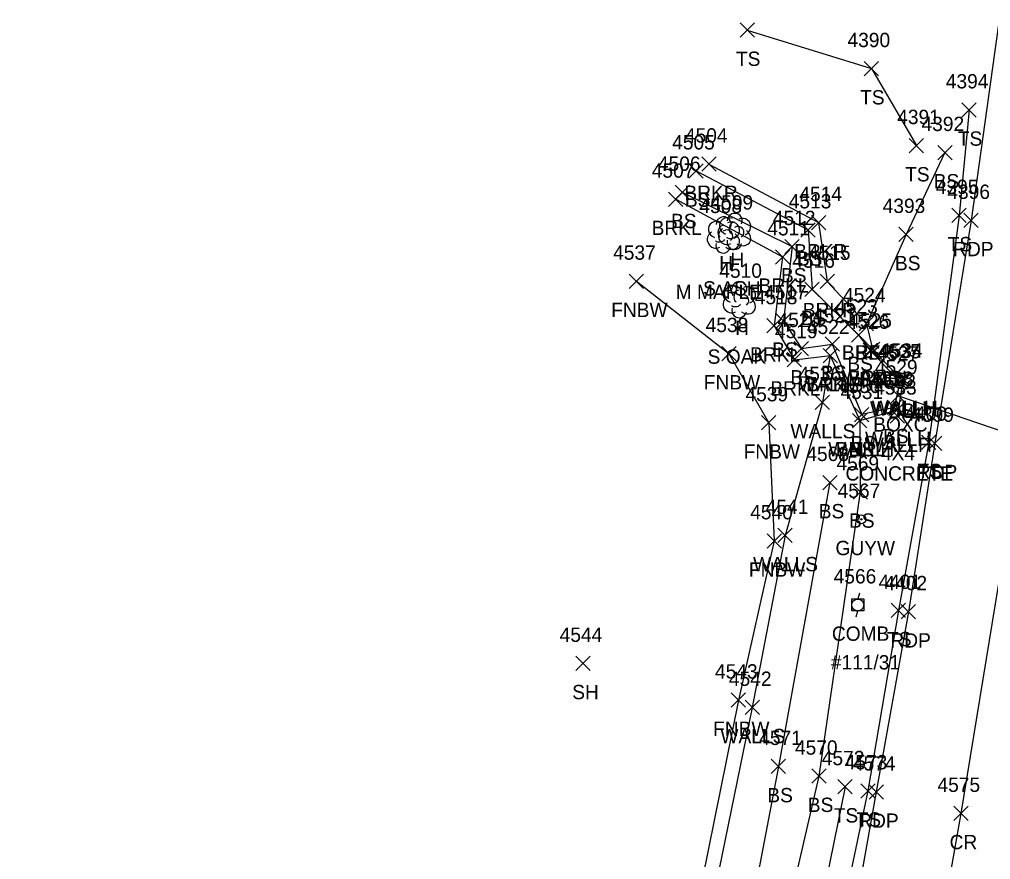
# Model space of a CAD drawing. Extents: x 1678863 to 1683592, y 407783 to 418211.
# Drawn here: x 1680132.2 to 1680267.7, y 412706.9 to 412824.2 of the extents above; entities that cross this region are included whole.
import ezdxf

# ---------------------------------------------------------------- set-up
doc = ezdxf.new("R2010")
doc.units = 0
for name, color, linetype in [('D_A', 7, 'Continuous'), ('D_C', 7, 'Continuous'), ('D_I', 7, 'Continuous'), ('D_TIC', 7, 'Continuous'), ('DDEFAULT', 7, 'Continuous'), ('DHW', 7, 'Continuous'), ('L_A', 7, 'Continuous'), ('L_C', 7, 'Continuous'), ('L_I', 7, 'Continuous'), ('L_TIC', 7, 'Continuous'), ('LAWE', 7, 'Continuous'), ('LELB', 7, 'Continuous'), ('LFNC', 7, 'Continuous'), ('LTD', 7, 'Continuous'), ('LWS', 7, 'Continuous'), ('P_A', 7, 'Continuous'), ('P_I', 7, 'Continuous'), ('P_TIC', 7, 'Continuous'), ('PET', 7, 'Continuous'), ('PRC', 7, 'Continuous'), ('U_A', 7, 'Continuous'), ('U_C', 7, 'Continuous'), ('U_I', 7, 'Continuous'), ('UP', 7, 'Continuous'), ('UPGW', 7, 'Continuous')]:
    doc.layers.add(name, color=color, linetype=linetype)

msp = doc.modelspace()

# ---------------------------------------------------------------- linework, layer by layer
at = {"layer": 'D_TIC'}
for points in [[(1680250.28, 412777.16), (1680252.28, 412779.16)], [(1680252.28, 412777.16), (1680250.28, 412779.16)], [(1680254.33, 412772.88), (1680256.33, 412774.88)], [(1680256.33, 412772.88), (1680254.33, 412774.88)], [(1680254.58, 412772.97), (1680256.58, 412774.97)], [(1680256.58, 412772.97), (1680254.58, 412774.97)], [(1680253.88, 412770.66), (1680255.88, 412772.66)], [(1680255.88, 412770.66), (1680253.88, 412772.66)], [(1680253.63, 412768.64), (1680255.63, 412770.64)], [(1680255.63, 412768.64), (1680253.63, 412770.64)], [(1680253.75, 412767.82), (1680255.75, 412769.82)], [(1680255.75, 412767.82), (1680253.75, 412769.82)], [(1680248.49, 412767.2), (1680250.49, 412769.2)], [(1680250.49, 412767.2), (1680248.49, 412769.2)]]:
    msp.add_lwpolyline(points, dxfattribs=at)
at = {"layer": 'DDEFAULT'}
msp.add_lwpolyline([(1680254.88, 412771.66), (1680298.09, 412756.89)], dxfattribs=at)
at = {"layer": 'DHW'}
for points in [[(1680251.28, 412778.16), (1680255.33, 412773.88)], [(1680254.75, 412768.82), (1680255.58, 412773.97)], [(1680249.49, 412768.2), (1680254.63, 412769.64)]]:
    msp.add_lwpolyline(points, dxfattribs=at)
at = {"layer": 'L_TIC'}
for points in [[(1680232.8, 412821.69), (1680234.8, 412823.69)], [(1680234.8, 412821.69), (1680232.8, 412823.69)], [(1680250.13, 412816.31), (1680252.13, 412818.31)], [(1680252.13, 412816.31), (1680250.13, 412818.31)], [(1680263.76, 412810.55), (1680265.76, 412812.55)], [(1680265.76, 412810.55), (1680263.76, 412812.55)], [(1680256.41, 412805.57), (1680258.41, 412807.57)], [(1680258.41, 412805.57), (1680256.41, 412807.57)], [(1680260.37, 412804.6), (1680262.37, 412806.6)], [(1680262.37, 412804.6), (1680260.37, 412806.6)], [(1680227.43, 412802.99), (1680229.43, 412804.99)], [(1680229.43, 412802.99), (1680227.43, 412804.99)], [(1680225.65, 412802.03), (1680227.65, 412804.03)], [(1680227.65, 412802.03), (1680225.65, 412804.03)], [(1680223.71, 412799.05), (1680225.71, 412801.05)], [(1680225.71, 412799.05), (1680223.71, 412801.05)], [(1680222.8, 412798.09), (1680224.8, 412800.09)], [(1680224.8, 412798.09), (1680222.8, 412800.09)], [(1680262.36, 412795.82), (1680264.36, 412797.82)], [(1680264.36, 412795.82), (1680262.36, 412797.82)], [(1680242.75, 412794.82), (1680244.75, 412796.82)], [(1680244.75, 412794.82), (1680242.75, 412796.82)], [(1680241.27, 412793.8), (1680243.27, 412795.8)], [(1680243.27, 412793.8), (1680241.27, 412795.8)], [(1680254.95, 412793.17), (1680256.95, 412795.17)], [(1680256.95, 412793.17), (1680254.95, 412795.17)], [(1680239.05, 412791.47), (1680241.05, 412793.47)], [(1680241.05, 412791.47), (1680239.05, 412793.47)], [(1680237.71, 412790.04), (1680239.71, 412792.04)], [(1680239.71, 412790.04), (1680237.71, 412792.04)], [(1680217.33, 412786.64), (1680219.33, 412788.64)], [(1680219.33, 412786.64), (1680217.33, 412788.64)], [(1680243.95, 412786.62), (1680245.95, 412788.62)], [(1680245.95, 412786.62), (1680243.95, 412788.62)], [(1680241.83, 412785.52), (1680243.83, 412787.52)], [(1680243.83, 412785.52), (1680241.83, 412787.52)], [(1680237.83, 412781.11), (1680239.83, 412783.11)], [(1680239.83, 412781.11), (1680237.83, 412783.11)], [(1680236.53, 412780.43), (1680238.53, 412782.43)], [(1680238.53, 412780.43), (1680236.53, 412782.43)], [(1680249.41, 412780.71), (1680251.41, 412782.71)], [(1680251.41, 412780.71), (1680249.41, 412782.71)], [(1680249.41, 412780.71), (1680251.41, 412782.71)], [(1680251.41, 412780.71), (1680249.41, 412782.71)], [(1680248.32, 412779.13), (1680250.32, 412781.13)], [(1680250.32, 412779.13), (1680248.32, 412781.13)], [(1680240.36, 412777.24), (1680242.36, 412779.24)], [(1680242.36, 412777.24), (1680240.36, 412779.24)], [(1680244.66, 412777.88), (1680246.66, 412779.88)], [(1680246.66, 412777.88), (1680244.66, 412779.88)], [(1680249.98, 412776.99), (1680251.98, 412778.99)], [(1680251.98, 412776.99), (1680249.98, 412778.99)], [(1680250.28, 412777.16), (1680252.28, 412779.16)], [(1680252.28, 412777.16), (1680250.28, 412779.16)], [(1680230.24, 412776.54), (1680232.24, 412778.54)], [(1680232.24, 412776.54), (1680230.24, 412778.54)], [(1680239.37, 412775.69), (1680241.37, 412777.69)], [(1680241.37, 412775.69), (1680239.37, 412777.69)], [(1680244.37, 412776.27), (1680246.37, 412778.27)], [(1680246.37, 412776.27), (1680244.37, 412778.27)], [(1680244.37, 412776.27), (1680246.37, 412778.27)], [(1680246.37, 412776.27), (1680244.37, 412778.27)], [(1680254.09, 412772.57), (1680256.09, 412774.57)], [(1680256.09, 412772.57), (1680254.09, 412774.57)], [(1680243.27, 412769.72), (1680245.27, 412771.72)], [(1680245.27, 412769.72), (1680243.27, 412771.72)], [(1680253.31, 412769.03), (1680255.31, 412771.03)], [(1680255.31, 412769.03), (1680253.31, 412771.03)], [(1680248.77, 412768.04), (1680250.77, 412770.04)], [(1680250.77, 412768.04), (1680248.77, 412770.04)], [(1680248.77, 412768.04), (1680250.77, 412770.04)], [(1680250.77, 412768.04), (1680248.77, 412770.04)], [(1680235.8, 412766.88), (1680237.8, 412768.88)], [(1680237.8, 412766.88), (1680235.8, 412768.88)], [(1680248.49, 412767.2), (1680250.49, 412769.2)], [(1680250.49, 412767.2), (1680248.49, 412769.2)], [(1680248.49, 412767.2), (1680250.49, 412769.2)], [(1680250.49, 412767.2), (1680248.49, 412769.2)], [(1680258.13, 412764.17), (1680260.13, 412766.17)], [(1680260.13, 412764.17), (1680258.13, 412766.17)], [(1680244.33, 412758.55), (1680246.33, 412760.55)], [(1680246.33, 412758.55), (1680244.33, 412760.55)], [(1680248.55, 412757.24), (1680250.55, 412759.24)], [(1680250.55, 412757.24), (1680248.55, 412759.24)], [(1680238.06, 412751.16), (1680240.06, 412753.16)], [(1680240.06, 412751.16), (1680238.06, 412753.16)], [(1680236.55, 412750.41), (1680238.55, 412752.41)], [(1680238.55, 412750.41), (1680236.55, 412752.41)], [(1680253.89, 412740.7), (1680255.89, 412742.7)], [(1680255.89, 412740.7), (1680253.89, 412742.7)], [(1680209.87, 412733.31), (1680211.87, 412735.31)], [(1680211.87, 412733.31), (1680209.87, 412735.31)], [(1680231.55, 412728.19), (1680233.55, 412730.19)], [(1680233.55, 412728.19), (1680231.55, 412730.19)], [(1680233.49, 412727.17), (1680235.49, 412729.17)], [(1680235.49, 412727.17), (1680233.49, 412729.17)], [(1680237.15, 412718.92), (1680239.15, 412720.92)], [(1680239.15, 412718.92), (1680237.15, 412720.92)], [(1680242.8, 412717.57), (1680244.8, 412719.57)], [(1680244.8, 412717.57), (1680242.8, 412719.57)], [(1680246.45, 412716.1), (1680248.45, 412718.1)], [(1680248.45, 412716.1), (1680246.45, 412718.1)], [(1680249.64, 412715.52), (1680251.64, 412717.52)], [(1680251.64, 412715.52), (1680249.64, 412717.52)]]:
    msp.add_lwpolyline(points, dxfattribs=at)
at = {"layer": 'LAWE'}
for points in [[(1680228.43, 412803.99), (1680243.75, 412795.82), (1680244.95, 412787.62), (1680250.41, 412781.71), (1680251.28, 412778.16)], [(1680223.8, 412799.09), (1680238.71, 412791.04), (1680237.53, 412781.43), (1680240.37, 412776.69), (1680245.37, 412777.27), (1680249.49, 412768.2)]]:
    msp.add_lwpolyline(points, dxfattribs=at)
at = {"layer": 'LELB'}
for points in [[(1680233.8, 412822.69), (1680251.13, 412817.31), (1680257.41, 412806.57)], [(1680264.76, 412811.55), (1680263.36, 412796.82), (1680259.13, 412765.17), (1680254.89, 412741.7), (1680250.64, 412716.52), (1680241.43, 412672.74), (1680233.74, 412632.17), (1680225.8, 412592.02), (1680220.98, 412567.08), (1680215.74, 412540.31), (1680209.94, 412509.25), (1680204.22, 412481.07), (1680197.27, 412449.21), (1680193.18, 412427.19), (1680186.13, 412390.36), (1680174.63, 412348.27), (1680162.56, 412311.44), (1680153.21, 412285.21), (1680144.52, 412262.81), (1680134.21, 412242.14)], [(1680261.37, 412805.6), (1680255.95, 412794.17), (1680250.41, 412781.71)], [(1680226.65, 412803.03), (1680242.27, 412794.8), (1680242.83, 412786.52), (1680249.32, 412780.13), (1680250.98, 412777.99), (1680255.09, 412773.57), (1680254.31, 412770.03), (1680249.77, 412769.04)], [(1680224.71, 412800.05), (1680240.05, 412792.47), (1680238.83, 412782.11), (1680241.36, 412778.24), (1680245.66, 412778.88), (1680249.77, 412769.04)], [(1680249.49, 412768.2), (1680249.55, 412758.24), (1680243.8, 412718.57), (1680233.25, 412673.09), (1680225.51, 412631.52), (1680218.17, 412594.23), (1680214.71, 412567.57), (1680210.01, 412541.36), (1680205.47, 412510.43), (1680201.22, 412481.17), (1680196.31, 412449.36), (1680192.42, 412427.44), (1680185.73, 412390.56), (1680174.21, 412348.31), (1680162.14, 412311.42), (1680152.66, 412285.29), (1680142.36, 412263.76), (1680132.21, 412242.7)], [(1680245.33, 412759.55), (1680238.15, 412719.92), (1680229.05, 412672.21), (1680221.09, 412632.34), (1680212.81, 412594.54), (1680208.5, 412568.01), (1680206.55, 412542.12), (1680201.64, 412511.16), (1680199.02, 412481.87), (1680194.17, 412449.89), (1680191.64, 412427.54), (1680187.79, 412410.87)], [(1680247.45, 412717.1), (1680238.47, 412672.98), (1680230.77, 412632.28), (1680223.41, 412592.33), (1680217.93, 412566.73), (1680212.88, 412540.48)]]:
    msp.add_lwpolyline(points, dxfattribs=at)
at = {"layer": 'LFNC'}
msp.add_lwpolyline([(1680218.33, 412787.64), (1680231.24, 412777.54), (1680236.8, 412767.88), (1680237.55, 412751.41), (1680232.55, 412729.19), (1680224.98, 412691.69), (1680216.02, 412647.3), (1680207.26, 412604.15), (1680201.33, 412570.32), (1680196.34, 412553.95), (1680191.84, 412524.59), (1680188.15, 412511.78), (1680185.17, 412500.91), (1680174.35, 412504.66)], dxfattribs=at)
at = {"layer": 'LTD'}
for p, q in [((1680230.45, 412794.15), (1680230.45, 412794.15)), ((1680230.45, 412794.15), (1680230.45, 412794.15)), ((1680232, 412794.64), (1680232, 412794.64)), ((1680232, 412794.64), (1680232, 412794.64)), ((1680232.67, 412785.12), (1680232.67, 412785.12)), ((1680232.67, 412785.12), (1680232.67, 412785.12))]:
    msp.add_line(p, q, dxfattribs=at)
for centre in [(1680230.49, 412795.58), (1680232.05, 412796.07), (1680232.71, 412786.55)]:
    msp.add_arc(centre, 1.05, 335.5272, 180.9563, dxfattribs=at)
for centre, major_axis, ratio, start_param, end_param in [((1680231.21, 412795.3), (1.21, -0.51), 0.895232, 1.570796, 4.712389), ((1680233.05, 412795.22), (-1.14, -0.48), 0.949671, 1.570796, 4.712389), ((1680229.66, 412794.82), (1.21, -0.51), 0.895232, 1.570796, 4.712389), ((1680230.24, 412794.61), (-0.208, -0.792), 0.645439, 3.141593, 6.283185), ((1680231.49, 412794.73), (-1.14, -0.48), 0.949671, 1.570796, 4.712389), ((1680231.8, 412795.09), (-0.208, -0.792), 0.645439, 3.141593, 6.283185), ((1680232.5, 412794.47), (-0.5, 0.667), 0.989748, 3.141593, 6.283185), ((1680229.36, 412793.44), (0.58, -1.04), 0.959034, 3.141593, 6.283185), ((1680230.92, 412793.93), (0.58, -1.04), 0.959034, 3.141593, 6.283185), ((1680230.95, 412793.98), (-0.5, 0.667), 0.989748, 3.141593, 6.283185), ((1680231.45, 412793.32), (-1.09, 0.79), 0.841452, 1.570796, 4.712389), ((1680231.55, 412793.88), (-0.625, -0.083), 0.423636, 0, 3.141593), ((1680233, 412793.8), (-1.09, 0.79), 0.841452, 1.570796, 4.712389), ((1680230.45, 412792.65), (0.26, 1.06), 0.942809, 1.570796, 4.712389), ((1680229.99, 412793.4), (-0.625, -0.083), 0.423636, 0, 3.141593), ((1680232, 412793.14), (0.26, 1.06), 0.942809, 1.570796, 4.712389), ((1680231.87, 412785.78), (1.21, -0.51), 0.895232, 1.570796, 4.712389), ((1680233.71, 412785.7), (-1.14, -0.48), 0.949671, 1.570796, 4.712389), ((1680232.46, 412785.58), (-0.208, -0.792), 0.645439, 3.141593, 6.283185), ((1680233.17, 412784.95), (-0.5, 0.667), 0.989748, 3.141593, 6.283185), ((1680231.58, 412784.41), (0.58, -1.04), 0.959034, 3.141593, 6.283185), ((1680232.21, 412784.37), (-0.625, -0.083), 0.423636, 0, 3.141593), ((1680233.67, 412784.28), (-1.09, 0.79), 0.841452, 1.570796, 4.712389), ((1680232.67, 412783.62), (0.26, 1.06), 0.942809, 1.570796, 4.712389)]:
    msp.add_ellipse(centre, major_axis=major_axis, ratio=ratio, start_param=start_param, end_param=end_param, dxfattribs=at)
at = {"layer": 'LWS'}
msp.add_lwpolyline([(1680245.37, 412777.27), (1680244.27, 412770.72), (1680239.06, 412752.16), (1680234.49, 412728.17), (1680226.88, 412691.09), (1680218.1, 412646.92), (1680208.94, 412603.49), (1680203.86, 412570.61), (1680197.52, 412543.94), (1680191.67, 412514.8), (1680187.87, 412497.52)], dxfattribs=at)
at = {"layer": 'P_TIC'}
for points in [[(1680264.04, 412795.13), (1680266.04, 412797.13)], [(1680266.04, 412795.13), (1680264.04, 412797.13)], [(1680258.96, 412764.02), (1680260.96, 412766.02)], [(1680260.96, 412764.02), (1680258.96, 412766.02)], [(1680255.28, 412740.52), (1680257.28, 412742.52)], [(1680257.28, 412740.52), (1680255.28, 412742.52)], [(1680250.79, 412715.36), (1680252.79, 412717.36)], [(1680252.79, 412715.36), (1680250.79, 412717.36)], [(1680262.6, 412712.37), (1680264.6, 412714.37)], [(1680264.6, 412712.37), (1680262.6, 412714.37)]]:
    msp.add_lwpolyline(points, dxfattribs=at)
at = {"layer": 'PET'}
msp.add_lwpolyline([(1680269.63, 412829.2), (1680265.04, 412796.13), (1680259.96, 412765.02), (1680256.28, 412741.52), (1680251.79, 412716.36), (1680243.91, 412672.27), (1680235.73, 412631.6), (1680228.05, 412591.55), (1680223.07, 412565.97), (1680218.11, 412539.91), (1680211.61, 412508.58), (1680205.85, 412480.93), (1680199.66, 412448.83), (1680195.01, 412427.07), (1680186.54, 412390.39), (1680175.26, 412348.31), (1680163.41, 412311.1), (1680153.81, 412285.2), (1680145.32, 412262.57), (1680136.24, 412241.39)], dxfattribs=at)
at = {"layer": 'PRC'}
msp.add_lwpolyline([(1680281.38, 412827.12), (1680276.54, 412794.32), (1680271.51, 412761.65), (1680263.6, 412713.37), (1680255.9, 412669.93), (1680248.46, 412629.97), (1680240.84, 412588.83), (1680235.69, 412562.84), (1680230.13, 412534.53), (1680222.13, 412495.39), (1680214.42, 412458.66), (1680203.73, 412409.82), (1680194.11, 412372.14), (1680183.59, 412335.84), (1680176.01, 412313.28), (1680165.53, 412283.79), (1680155.94, 412258.65)], dxfattribs=at)
at = {"layer": 'UP'}
for p, q in [((1680249.47, 412744.13), (1680249.22, 412743.3)), ((1680248.38, 412741.63), (1680248.38, 412743.3)), ((1680248.38, 412743.3), (1680250.05, 412743.3)), ((1680249.22, 412742.46), (1680249.22, 412742.46)), ((1680250.05, 412743.3), (1680250.05, 412741.63)), ((1680250.05, 412741.63), (1680248.38, 412741.63)), ((1680248.97, 412740.8), (1680249.22, 412741.63))]:
    msp.add_line(p, q, dxfattribs=at)
msp.add_circle((1680249.22, 412742.46), 0.833, dxfattribs=at)
at = {"layer": 'UPGW'}
for radius in [0.625, 0.0833]:
    msp.add_circle((1680249.7, 412754.41), radius, dxfattribs=at)

# ---------------------------------------------------------------- texts
at = {"layer": 'D_A'}
for s, p in [('WALLH', (1680246.87, 412773.16)), ('WALLH', (1680250.92, 412768.88)), ('WALLH', (1680251.17, 412768.97)), ('BOXC', (1680251.37, 412766.66)), ('WALLH', (1680250.23, 412764.64)), ('WALLH', (1680245.09, 412763.2)), ('WALLH', (1680250.34, 412763.82))]:
    msp.add_text(s, height=2, dxfattribs=at).set_placement(p)
at = {"layer": 'D_C'}
for s, p in [('4X4', (1680252.45, 412762.66)), ('CONCRETE', (1680247.5, 412759.82))]:
    msp.add_text(s, height=2, dxfattribs=at).set_placement(p)
at = {"layer": 'D_I'}
for s, p in [('4525', (1680248.02, 412781.16)), ('4535', (1680252.07, 412776.88)), ('4534', (1680252.32, 412776.97)), ('4529', (1680251.61, 412774.66)), ('4532', (1680251.37, 412772.64)), ('4533', (1680251.49, 412771.82)), ('4531', (1680246.8, 412771.2))]:
    msp.add_text(s, height=2, dxfattribs=at).set_placement(p)
at = {"layer": 'L_A'}
for s, p in [('TS', (1680232.21, 412817.69)), ('TS', (1680249.54, 412812.31)), ('TS', (1680263.17, 412806.55)), ('TS', (1680255.82, 412801.57)), ('BS', (1680259.81, 412800.6)), ('BRKR', (1680225.02, 412798.99)), ('BS', (1680225.09, 412798.03)), ('BS', (1680223.15, 412795.05)), ('BRKL', (1680220.44, 412794.09)), ('TS', (1680261.76, 412791.82)), ('BRKR', (1680240.34, 412790.82)), ('H', (1680229.88, 412789.15)), ('H', (1680231.44, 412789.64)), ('BS', (1680240.71, 412789.8)), ('BS', (1680254.4, 412789.17)), ('BS', (1680238.49, 412787.47)), ('BRKL', (1680235.36, 412786.04)), ('FNBW', (1680214.8, 412782.64)), ('BRKR', (1680241.54, 412782.62)), ('BS', (1680241.27, 412781.52)), ('H', (1680232.1, 412780.12)), ('BS', (1680237.27, 412777.11)), ('BRKR', (1680247, 412776.71)), ('BS', (1680248.85, 412776.71)), ('BRKL', (1680234.18, 412776.43)), ('BS', (1680247.76, 412775.13)), ('BS', (1680239.8, 412773.24)), ('BS', (1680244.1, 412773.88)), ('BRKR', (1680247.87, 412773.16)), ('BS', (1680249.42, 412772.99)), ('FNBW', (1680227.72, 412772.54)), ('BRKL', (1680237.01, 412771.69)), ('WALLS', (1680240.91, 412772.27)), ('BRKL', (1680242.02, 412772.27)), ('BS', (1680253.54, 412768.57)), ('WALLS', (1680239.81, 412765.72)), ('BS', (1680252.75, 412765.03)), ('BRKL', (1680246.14, 412763.2)), ('BS', (1680247.94, 412763.2)), ('BS', (1680248.21, 412764.04)), ('BS', (1680248.21, 412764.04)), ('FNBW', (1680233.28, 412762.88)), ('TS', (1680257.54, 412760.17)), ('BS', (1680243.77, 412754.55)), ('BS', (1680247.99, 412753.24)), ('WALLS', (1680234.6, 412747.16)), ('FNBW', (1680234.02, 412746.41)), ('TS', (1680253.3, 412736.7)), ('SH', (1680209.36, 412729.31)), ('FNBW', (1680229.02, 412724.19)), ('WALLS', (1680230.04, 412723.17)), ('BS', (1680236.59, 412714.92)), ('BS', (1680242.24, 412713.57)), ('TS', (1680245.86, 412712.1)), ('TS', (1680249.05, 412711.52))]:
    msp.add_text(s, height=2, dxfattribs=at).set_placement(p)
at = {"layer": 'L_C'}
for s, p in [('M MAPLE', (1680223.8, 412785.15)), ('S ASH', (1680227.63, 412785.64)), ('S OAK', (1680228.26, 412776.12))]:
    msp.add_text(s, height=2, dxfattribs=at).set_placement(p)
at = {"layer": 'L_I'}
for s, p in [('4390', (1680247.78, 412820.31)), ('4394', (1680261.5, 412814.55)), ('4391', (1680254.72, 412809.57)), ('4392', (1680258.11, 412808.6)), ('4504', (1680225.09, 412806.99)), ('4505', (1680223.31, 412806.03)), ('4506', (1680221.32, 412803.05)), ('4507', (1680220.46, 412802.09)), ('4395', (1680260.1, 412799.82)), ('4514', (1680241.06, 412798.82)), ('4508', (1680227.11, 412797.15)), ('4509', (1680228.66, 412797.64)), ('4513', (1680239.58, 412797.8)), ('4393', (1680252.69, 412797.17)), ('4512', (1680237.36, 412795.47)), ('4511', (1680236.59, 412794.04)), ('4537', (1680215.07, 412790.64)), ('4515', (1680242.25, 412790.62)), ('4516', (1680240.08, 412789.52)), ('4510', (1680229.89, 412788.12)), ('4517', (1680236.14, 412785.11)), ('4518', (1680234.84, 412784.43)), ('4524', (1680247.15, 412784.71)), ('4524', (1680247.15, 412784.71)), ('4523', (1680246.06, 412783.13)), ('4520', (1680238.01, 412781.24)), ('4521', (1680242.97, 412781.88)), ('4526', (1680247.66, 412780.99)), ('4525', (1680248.02, 412781.16)), ('4538', (1680227.98, 412780.54)), ('4519', (1680237.66, 412779.69)), ('4522', (1680242.11, 412780.27)), ('4522', (1680242.11, 412780.27)), ('4527', (1680251.83, 412776.57)), ('4536', (1680240.95, 412773.72)), ('4528', (1680251.05, 412773.03)), ('4530', (1680246.42, 412772.04)), ('4530', (1680246.42, 412772.04)), ('4539', (1680233.54, 412770.88)), ('4531', (1680246.8, 412771.2)), ('4531', (1680246.8, 412771.2)), ('4400', (1680255.7, 412768.17)), ('4568', (1680242.03, 412762.55)), ('4569', (1680246.24, 412761.24)), ('4541', (1680236.37, 412755.16)), ('4540', (1680234.2, 412754.41)), ('4401', (1680252.12, 412744.7)), ('4544', (1680207.61, 412737.31)), ('4543', (1680229.29, 412732.19)), ('4542', (1680231.23, 412731.17)), ('4571', (1680235.46, 412722.92)), ('4570', (1680240.45, 412721.57)), ('4572', (1680244.19, 412720.1)), ('4573', (1680247.38, 412719.52))]:
    msp.add_text(s, height=2, dxfattribs=at).set_placement(p)
at = {"layer": 'P_A'}
for s, p in [('RDP', (1680262.52, 412791.13)), ('RDP', (1680257.45, 412760.02)), ('RDP', (1680253.77, 412736.52)), ('RDP', (1680249.28, 412711.36)), ('CR', (1680262.03, 412708.37))]:
    msp.add_text(s, height=2, dxfattribs=at).set_placement(p)
at = {"layer": 'P_I'}
for s, p in [('4396', (1680261.72, 412799.13)), ('4399', (1680256.69, 412768.02)), ('4402', (1680252.94, 412744.52)), ('4574', (1680248.53, 412719.36)), ('4575', (1680260.34, 412716.37))]:
    msp.add_text(s, height=2, dxfattribs=at).set_placement(p)
at = {"layer": 'U_A'}
for s, p in [('GUYW', (1680246.1, 412749.41)), ('COMB', (1680245.6, 412737.46))]:
    msp.add_text(s, height=2, dxfattribs=at).set_placement(p)
at = {"layer": 'U_C'}
msp.add_text('#111/31', height=2, dxfattribs=at).set_placement((1680245.45, 412733.46))
at = {"layer": 'U_I'}
for s, p in [('4567', (1680246.4, 412757.41)), ('4566', (1680245.85, 412745.46))]:
    msp.add_text(s, height=2, dxfattribs=at).set_placement(p)

doc.saveas('drawing.dxf')
